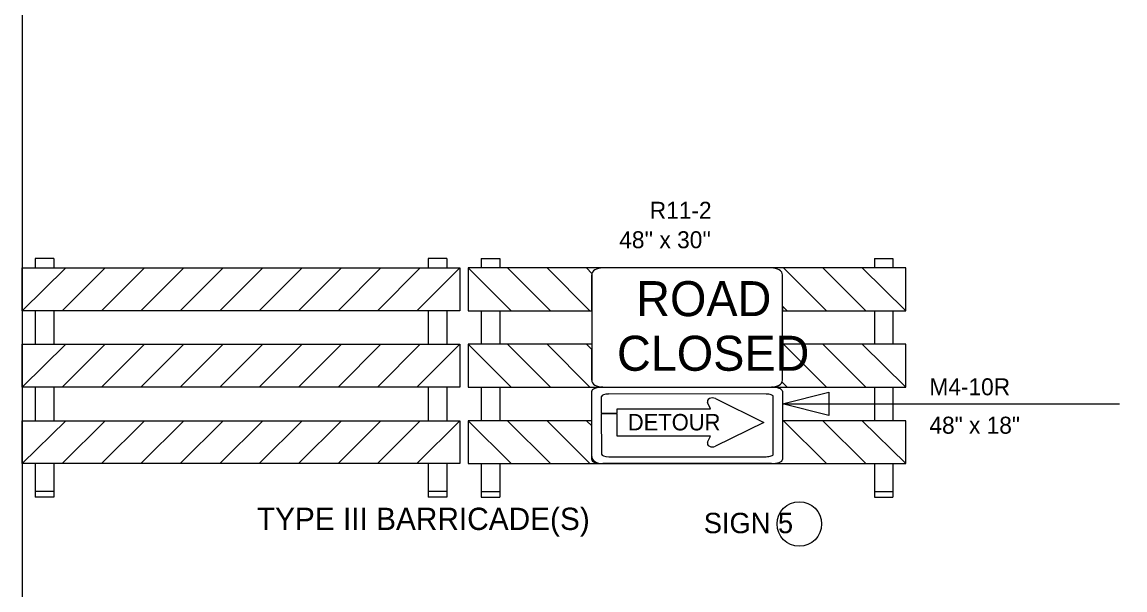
# Model space of a CAD drawing. Extents: x 1613335 to 1618399, y 897277 to 901877.
# Drawn here: x 1613974 to 1615143, y 899179 to 899781 of the extents above; entities that cross this region are included whole.
import ezdxf

# ---------------------------------------------------------------- set-up
doc = ezdxf.new("R2010")
doc.units = 0
for name, color, linetype in [('DEV TYPE 3 BARRICADE DOUBLE WITH R11-2 CELL', 7, 'Continuous'), ('DEV TYPE 3 BARRICADE WITH R11-2 M4-10R CELL', 7, 'Continuous'), ('Old_Level_28', 7, 'Continuous'), ('Scratch_Level_0', 7, 'Continuous')]:
    doc.layers.add(name, color=color, linetype=linetype)

msp = doc.modelspace()

# ---------------------------------------------------------------- linework, layer by layer
at = {"layer": 'DEV TYPE 3 BARRICADE DOUBLE WITH R11-2 CELL'}
for p, q in [((1614007.1, 899530.5), (1613987.3, 899530.5)), ((1613987.3, 899530.5), (1613987.3, 899520.7)), ((1614007.1, 899530.5), (1614007.1, 899520.7)), ((1614424, 899530.5), (1614404.3, 899530.5)), ((1614404.3, 899530.5), (1614404.3, 899520.7)), ((1614424, 899530.5), (1614424, 899520.7)), ((1614460.6, 899530.5), (1614480.3, 899530.5)), ((1614460.6, 899530.5), (1614460.6, 899520.7)), ((1614480.3, 899530.5), (1614480.3, 899520.7)), ((1614877.6, 899530.5), (1614897.3, 899530.5)), ((1614877.6, 899530.5), (1614877.6, 899520.7)), ((1614897.3, 899530.5), (1614897.3, 899520.7)), ((1613973.6, 899520.7), (1614437.8, 899520.7)), ((1613973.6, 899475.2), (1613973.6, 899520.7)), ((1613973.6, 899475.2), (1613973.6, 899520.7)), ((1613973.6, 899520.7), (1614019.9, 899520.7)), ((1614019.9, 899520.7), (1613973.6, 899475.2)), ((1614016.1, 899475.2), (1614061.6, 899520.7)), ((1614103.4, 899520.7), (1614057.9, 899475.2)), ((1614061.6, 899520.7), (1614103.4, 899520.7)), ((1614099.7, 899475.2), (1614145.2, 899520.7)), ((1614187, 899520.7), (1614141.4, 899475.2)), ((1614145.2, 899520.7), (1614187, 899520.7)), ((1614183.4, 899475.2), (1614228.9, 899520.7)), ((1614270.7, 899520.7), (1614225.2, 899475.2)), ((1614228.9, 899520.7), (1614270.7, 899520.7)), ((1614266.9, 899475.2), (1614312.5, 899520.7)), ((1614354.2, 899520.7), (1614308.7, 899475.2)), ((1614312.5, 899520.7), (1614354.2, 899520.7)), ((1614350.5, 899475.2), (1614396, 899520.7)), ((1614437.8, 899520.7), (1614392.3, 899475.2)), ((1614396, 899520.7), (1614437.8, 899520.7)), ((1614437.8, 899520.7), (1614437.8, 899475.2)), ((1614911.1, 899520.7), (1614446.8, 899520.7)), ((1614446.8, 899520.7), (1614446.8, 899475.2)), ((1614488.6, 899520.7), (1614446.8, 899520.7)), ((1614446.8, 899520.7), (1614492.4, 899475.2)), ((1614534.1, 899475.2), (1614488.6, 899520.7)), ((1614572.2, 899520.7), (1614530.4, 899520.7)), ((1614530.4, 899520.7), (1614575.9, 899475.2)), ((1614578, 899514.8), (1614572.2, 899520.7)), ((1614577.8, 899475.2), (1614577.8, 899513.3)), ((1614823, 899520.7), (1614781.2, 899520.7)), ((1614781.2, 899520.7), (1614826.7, 899475.2)), ((1614868.5, 899475.2), (1614823, 899520.7)), ((1614911.1, 899520.7), (1614864.8, 899520.7)), ((1614864.8, 899520.7), (1614911.1, 899475.2)), ((1614911.1, 899475.2), (1614911.1, 899520.7)), ((1614911.1, 899475.2), (1614911.1, 899520.7)), ((1614785, 899475.2), (1614780.2, 899480)), ((1614780.2, 899480), (1614780.2, 899475.2)), ((1614437.8, 899475.2), (1613973.6, 899475.2)), ((1613987.3, 899475.2), (1613987.3, 899439.7)), ((1614007.1, 899475.2), (1614007.1, 899439.7)), ((1614057.9, 899475.2), (1614016.1, 899475.2)), ((1614141.4, 899475.2), (1614099.7, 899475.2)), ((1614225.2, 899475.2), (1614183.4, 899475.2)), ((1614308.7, 899475.2), (1614266.9, 899475.2)), ((1614392.3, 899475.2), (1614350.5, 899475.2)), ((1614404.3, 899475.2), (1614404.3, 899439.7)), ((1614424, 899475.2), (1614424, 899439.7)), ((1614446.8, 899475.2), (1614577.8, 899475.2)), ((1614460.6, 899475.2), (1614460.6, 899439.7)), ((1614480.3, 899475.2), (1614480.3, 899439.7)), ((1614492.4, 899475.2), (1614534.1, 899475.2)), ((1614575.9, 899475.2), (1614577.8, 899475.2)), ((1614780.2, 899475.2), (1614785, 899475.2)), ((1614780.2, 899475.2), (1614911.1, 899475.2)), ((1614826.7, 899475.2), (1614868.5, 899475.2)), ((1614877.6, 899475.2), (1614877.6, 899439.7)), ((1614897.3, 899475.2), (1614897.3, 899439.7)), ((1613973.6, 899439.7), (1614437.8, 899439.7)), ((1613973.6, 899394.2), (1613973.6, 899439.7)), ((1613973.6, 899394.2), (1613973.6, 899439.7)), ((1613973.6, 899439.7), (1614019.9, 899439.7)), ((1614019.9, 899439.7), (1613973.6, 899394.2)), ((1614016.1, 899394.2), (1614061.6, 899439.7)), ((1614103.4, 899439.7), (1614057.9, 899394.2)), ((1614061.6, 899439.7), (1614103.4, 899439.7)), ((1614099.7, 899394.2), (1614145.2, 899439.7)), ((1614187, 899439.7), (1614141.4, 899394.2)), ((1614145.2, 899439.7), (1614187, 899439.7)), ((1614183.4, 899394.2), (1614228.9, 899439.7)), ((1614270.7, 899439.7), (1614225.2, 899394.2)), ((1614228.9, 899439.7), (1614270.7, 899439.7)), ((1614266.9, 899394.2), (1614312.5, 899439.7)), ((1614354.2, 899439.7), (1614308.7, 899394.2)), ((1614312.5, 899439.7), (1614354.2, 899439.7)), ((1614350.5, 899394.2), (1614396, 899439.7)), ((1614437.8, 899439.7), (1614392.3, 899394.2)), ((1614396, 899439.7), (1614437.8, 899439.7)), ((1614437.8, 899439.7), (1614437.8, 899394.2)), ((1614446.8, 899439.7), (1614446.8, 899394.2)), ((1614488.6, 899439.7), (1614446.8, 899439.7)), ((1614446.8, 899439.7), (1614492.4, 899394.2)), ((1614577.8, 899439.7), (1614446.8, 899439.7)), ((1614534.1, 899394.2), (1614488.6, 899439.7)), ((1614530.4, 899439.7), (1614575.9, 899394.2)), ((1614572.2, 899439.7), (1614530.4, 899439.7)), ((1614577.8, 899434.1), (1614572.2, 899439.7)), ((1614577.8, 899401.6), (1614577.8, 899434.1)), ((1614911.1, 899439.7), (1614780.2, 899439.7)), ((1614823, 899439.7), (1614781.2, 899439.7)), ((1614781.2, 899439.7), (1614826.7, 899394.2)), ((1614868.5, 899394.2), (1614823, 899439.7)), ((1614911.1, 899439.7), (1614864.8, 899439.7)), ((1614864.8, 899439.7), (1614911.1, 899394.2)), ((1614911.1, 899394.2), (1614911.1, 899439.7)), ((1614911.1, 899394.2), (1614911.1, 899439.7)), ((1614785, 899394.2), (1614779.7, 899399.5)), ((1614437.8, 899394.2), (1613973.6, 899394.2)), ((1613987.3, 899394.2), (1613987.3, 899358.7)), ((1614007.1, 899394.2), (1614007.1, 899358.7)), ((1614057.9, 899394.2), (1614016.1, 899394.2)), ((1614141.4, 899394.2), (1614099.7, 899394.2)), ((1614225.2, 899394.2), (1614183.4, 899394.2)), ((1614308.7, 899394.2), (1614266.9, 899394.2)), ((1614392.3, 899394.2), (1614350.5, 899394.2)), ((1614404.3, 899394.2), (1614404.3, 899358.7)), ((1614424, 899394.2), (1614424, 899358.7)), ((1614446.8, 899394.2), (1614911.1, 899394.2)), ((1614460.6, 899394.2), (1614460.6, 899358.7)), ((1614480.3, 899394.2), (1614480.3, 899358.7)), ((1614492.4, 899394.2), (1614534.1, 899394.2)), ((1614575.9, 899394.2), (1614589.5, 899394.2)), ((1614589.6, 899394.2), (1614768.4, 899394.2)), ((1614768.4, 899394.2), (1614785, 899394.2)), ((1614826.7, 899394.2), (1614868.5, 899394.2)), ((1614877.6, 899394.2), (1614877.6, 899358.7)), ((1614897.3, 899394.2), (1614897.3, 899358.7)), ((1613973.6, 899358.7), (1614437.8, 899358.7)), ((1613973.6, 899313.2), (1613973.6, 899358.7)), ((1613973.6, 899358.7), (1614019.9, 899358.7)), ((1614019.9, 899358.7), (1613973.6, 899313.2)), ((1613973.6, 899313.2), (1613973.6, 899358.7)), ((1614016.1, 899313.2), (1614061.6, 899358.7)), ((1614103.4, 899358.7), (1614057.9, 899313.2)), ((1614061.6, 899358.7), (1614103.4, 899358.7)), ((1614099.7, 899313.2), (1614145.2, 899358.7)), ((1614187, 899358.7), (1614141.4, 899313.2)), ((1614145.2, 899358.7), (1614187, 899358.7)), ((1614183.4, 899313.2), (1614228.9, 899358.7)), ((1614270.7, 899358.7), (1614225.2, 899313.2)), ((1614228.9, 899358.7), (1614270.7, 899358.7)), ((1614266.9, 899313.2), (1614312.5, 899358.7)), ((1614354.2, 899358.7), (1614308.7, 899313.2)), ((1614312.5, 899358.7), (1614354.2, 899358.7)), ((1614350.5, 899313.2), (1614396, 899358.7)), ((1614437.8, 899358.7), (1614392.3, 899313.2)), ((1614396, 899358.7), (1614437.8, 899358.7)), ((1614437.8, 899358.7), (1614437.8, 899313.2)), ((1614488.6, 899358.7), (1614446.8, 899358.7)), ((1614446.8, 899358.7), (1614492.4, 899313.2)), ((1614446.8, 899358.7), (1614446.8, 899313.2)), ((1614577.8, 899358.7), (1614446.8, 899358.7)), ((1614534.1, 899313.2), (1614488.6, 899358.7)), ((1614911.1, 899358.7), (1614780.2, 899358.7)), ((1614823, 899358.7), (1614781.2, 899358.7)), ((1614781.2, 899358.7), (1614826.7, 899313.2)), ((1614868.5, 899313.2), (1614823, 899358.7)), ((1614911.1, 899358.7), (1614864.8, 899358.7)), ((1614864.8, 899358.7), (1614911.1, 899313.2)), ((1614911.1, 899313.2), (1614911.1, 899358.7)), ((1614911.1, 899313.2), (1614911.1, 899358.7)), ((1614437.8, 899313.2), (1613973.6, 899313.2)), ((1613987.3, 899313.2), (1613987.3, 899277.7)), ((1614007.1, 899313.2), (1614007.1, 899277.7)), ((1614057.9, 899313.2), (1614016.1, 899313.2)), ((1614141.4, 899313.2), (1614099.7, 899313.2)), ((1614225.2, 899313.2), (1614183.4, 899313.2)), ((1614308.7, 899313.2), (1614266.9, 899313.2)), ((1614392.3, 899313.2), (1614350.5, 899313.2)), ((1614404.3, 899313.2), (1614404.3, 899277.7)), ((1614424, 899313.2), (1614424, 899277.7)), ((1614446.8, 899313.2), (1614911.1, 899313.2)), ((1614460.6, 899313.2), (1614460.6, 899277.7)), ((1614480.3, 899313.2), (1614480.3, 899277.7)), ((1614492.4, 899313.2), (1614534.1, 899313.2)), ((1614826.7, 899313.2), (1614868.5, 899313.2)), ((1614877.6, 899313.2), (1614877.6, 899277.7)), ((1614897.3, 899313.2), (1614897.3, 899277.7)), ((1614007.1, 899283.7), (1613987.3, 899283.7)), ((1614424, 899283.7), (1614404.3, 899283.7)), ((1614460.6, 899283.7), (1614480.3, 899283.7)), ((1614877.6, 899283.7), (1614897.3, 899283.7)), ((1614007.1, 899277.7), (1613987.3, 899277.7)), ((1614424, 899277.7), (1614404.3, 899277.7)), ((1614460.6, 899277.7), (1614480.3, 899277.7)), ((1614877.6, 899277.7), (1614897.3, 899277.7))]:
    msp.add_line(p, q, dxfattribs=at)
for points in [[(1614577.8, 899513.3), (1614577.8, 899401.6)], [(1614768.4, 899520.7), (1614589.6, 899520.7)], [(1614780.2, 899401.6), (1614780.2, 899513.3)]]:
    msp.add_lwpolyline(points, dxfattribs=at)
for centre, major_axis, start_param, end_param in [((1614589.6, 899513.3), (-11.8, 0), 4.712389, 6.283185), ((1614589.6, 899513.3), (-11.8, 0), 6.074789, 6.283185), ((1614768.4, 899513.3), (11.8, 0), 0, 1.571024), ((1614589.6, 899401.6), (11.8, 0), 3.141593, 4.712389), ((1614589.6, 899401.6), (-11.8, 0), 0, 1.570796), ((1614768.4, 899401.6), (11.8, 0), 4.712162, 6.283185), ((1614768.4, 899401.6), (11.8, 0), 4.712497, 5.996053)]:
    msp.add_ellipse(centre, major_axis=major_axis, ratio=0.625, start_param=start_param, end_param=end_param, dxfattribs=at)
at = {"layer": 'DEV TYPE 3 BARRICADE WITH R11-2 M4-10R CELL'}
for p, q in [((1614587.9, 899384.4), (1614587.9, 899366.5)), ((1614762.8, 899386.9), (1614595.6, 899387.1)), ((1614770.3, 899323.1), (1614770.3, 899384.4)), ((1614703.7, 899371.3), (1614700.7, 899377.8)), ((1614709, 899382.3), (1614760.2, 899356.7)), ((1614780.2, 899376.5), (1615137.6, 899376.5)), ((1614587.9, 899366.5), (1614604.7, 899366.5)), ((1614604.7, 899365.9), (1614587.9, 899365.9)), ((1614587.9, 899365.9), (1614588.1, 899323.1)), ((1614604.7, 899366.5), (1614604.7, 899371.3)), ((1614604.7, 899371.3), (1614703.7, 899371.3)), ((1614604.7, 899342.4), (1614604.7, 899365.9)), ((1614530.4, 899358.7), (1614575.9, 899313.2)), ((1614572.2, 899358.7), (1614530.4, 899358.7)), ((1614577.8, 899353.1), (1614572.2, 899358.7)), ((1614577.8, 899320.6), (1614577.8, 899353.1)), ((1614760.2, 899356.7), (1614709, 899331.6)), ((1614703.7, 899342.4), (1614604.7, 899342.4)), ((1614700.7, 899336), (1614703.7, 899342.4)), ((1614595.8, 899320.5), (1614762.8, 899320.5)), ((1614575.9, 899313.2), (1614589.5, 899313.2)), ((1614768.4, 899313.2), (1614589.6, 899313.2))]:
    msp.add_line(p, q, dxfattribs=at)
for points in [[(1614577.8, 899317.6), (1614577.8, 899389.8)], [(1614589.6, 899394.2), (1614768.4, 899394.2)], [(1614780.2, 899389.8), (1614780.2, 899317.6)]]:
    msp.add_lwpolyline(points, dxfattribs=at)
msp.add_lwpolyline([(1614829.4, 899364.2), (1614780.2, 899376.5), (1614829.4, 899388.8)], close=True, dxfattribs=at)
msp.add_lwpolyline([(1614829.4, 899364.2), (1614780.2, 899376.5), (1614829.4, 899388.8)], close=True, dxfattribs=at)
for centre, major_axis, ratio, start_param, end_param in [((1614589.6, 899389.8), (-11.8, 0), 0.375009, 4.712162, 6.283185), ((1614595.7, 899384.4), (-7.59, 0), 0.337508, 4.712581, 6.283188), ((1614762.7, 899384.4), (7.59, 0), 0.337508, 6.283178, 7.854173), ((1614768.4, 899389.8), (11.8, 0), 0.375009, 0, 1.570796), ((1614705.9, 899378.9), (5.42, 0), 0.720018, 0.96961, 3.452569), ((1614705.9, 899334.8), (5.42, 0), 0.720018, 2.830617, 5.313577), ((1614589.6, 899320.6), (11.8, 0), 0.625, 3.141593, 4.712389), ((1614589.6, 899317.6), (-11.8, 0), 0.375009, 0, 1.570796), ((1614595.8, 899323.1), (-7.59, 0), 0.337508, 0.000003, 1.57061), ((1614762.8, 899323.1), (7.59, 0), 0.337508, 4.712203, 6.283178), ((1614768.4, 899317.6), (-11.8, 0), 0.375009, 1.570796, 3.141593)]:
    msp.add_ellipse(centre, major_axis=major_axis, ratio=ratio, start_param=start_param, end_param=end_param, dxfattribs=at)
at = {"layer": 'Old_Level_28'}
msp.add_circle((1614798, 899249.2), 23.6, dxfattribs=at)
at = {"layer": 'Scratch_Level_0'}
msp.add_lwpolyline([(1618173.6, 901652.3), (1613973.6, 901652.3), (1613973.6, 898802.3), (1616610.1, 898802.3), (1616610.1, 899157.1), (1618173.6, 899157.1)], close=True, dxfattribs=at)

# ---------------------------------------------------------------- texts
at = {"layer": 'DEV TYPE 3 BARRICADE DOUBLE WITH R11-2 CELL'}
for s, height, p in [('R11-2', 18, (1614639.4, 899572.7)), ("48'' x 30''", 18, (1614607, 899541.5)), ('ROAD', 37.11, (1614625, 899469.5)), ('CLOSED', 37.11, (1614604.6, 899411.6)), ('TYPE III BARRICADE(S)', 23.645, (1614222.6, 899242.8))]:
    msp.add_text(s, height=height, rotation=360, dxfattribs=at).set_placement(p)
at = {"layer": 'DEV TYPE 3 BARRICADE WITH R11-2 M4-10R CELL'}
for s, p in [('M4-10R', (1614936, 899385.6)), ('48" x 18"', (1614936, 899344.9))]:
    msp.add_text(s, height=18, dxfattribs=at).set_placement(p)
msp.add_text('DETOUR', height=17.4, rotation=360, dxfattribs=at).set_placement((1614616.1, 899348.4))
at = {"layer": 'Old_Level_28'}
msp.add_text('SIGN 5', height=21.6, dxfattribs=at).set_placement((1614696.7, 899239.4))

doc.saveas('drawing.dxf')
